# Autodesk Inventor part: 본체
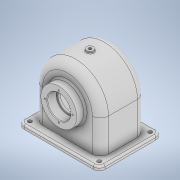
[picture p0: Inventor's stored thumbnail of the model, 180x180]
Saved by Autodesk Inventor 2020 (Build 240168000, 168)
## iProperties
Created: 2022-09
Part Number: 본체
Material: 일반
Document SubType Name: Modeling
Designer: Administrator
Density: 1 g/cm^3
Appearance: 기본값
Mass: 290.05 g
Surface Area: 1046.65 cm^2
Volume: 290.05 cm^3
Author: Administrator
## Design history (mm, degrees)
sketch "스케치1"
  geometry: L1 (70, -54)-(-70, -54); L2 (-70, -54)-(-70, 54); L3 (-70, 54)-(70, 54); L4 (70, 54)-(70, -54); L5 (70, -54)-(-70, 54); L6 (-70, -54)-(70, 54); 1 further point
  constraints: 12 end point, 2 midpoint, 2 parallel, 1 horizontal, 1 perpendicular
  dimensions: "d0" = 140 distance of L2.end L3.end; "d1" = 108 distance of L1.end L2.end
extrude "돌출1" new body sketch "스케치1" distance "d2" = 7; taper "d3" = 0 deg
sketch "스케치2"
  geometry: L1 (70, 0)-(-70, 0) reference; L2 (57, 64)-(57, 3); L3 (-57, 64)-(-57, 3); L4 (-70, 7)-(70, 7) reference; A1 r 57 centre (0, 64) between (57, 64) and (-57, 64); 3 further points
  constraints: 4 end point, 2 point on circle, 2 tangent, 2 vertical, 1 centre point, 1 vertical alignment
  dimensions: "d4" = 114 diameter of A1; "d5" = 64 distance from line of L1 A1.centre
extrude "돌출2" new body sketch "스케치2" stored distance "d6" = 78; taper "d7" = 0 deg
fillet "모깎기1" dims "d8" = 14
feature "쉘1" dims "d9" = 5
sketch "스케치3"
  geometry: L1 (-43, -39)-(43, -39) reference; L2 (57, -25)-(-57, -25) reference; L3 (-57, 25)-(57, 25) reference; L4 (-57, 25)-(-57, -25) reference; L5 (57, -25)-(-57, -25) reference; L6 (57, 25)-(57, -25) reference; L7 (43, 39)-(-43, 39) reference; L8 (-57, 25)-(57, 25) reference; L9 (-43, 34)-(43, 34) reference; L10 (-52, 25)-(-52, -25) reference; L11 (43, -34)-(-43, -34) reference; L12 (52, 25)-(52, -25) reference; A1 r 14 centre (-43, -25) between (-57, -25) and (-43, -39) reference; A2 r 14 centre (43, -25) between (43, -39) and (57, -25) reference; A3 r 14 centre (43, 25) between (57, 25) and (43, 39) reference; A4 r 14 centre (-43, 25) between (-43, 39) and (-57, 25) reference; A5 r 9 centre (-43, -25) between (-52, -25) and (-43, -34) reference; A6 r 9 centre (-43, 25) between (-43, 34) and (-52, 25) reference; A7 r 9 centre (43, -25) between (43, -34) and (52, -25) reference; A8 r 9 centre (43, 25) between (52, 25) and (43, 34) reference; 1 further point
extrude "돌출3" cut sketch "스케치3" distance "d10" = 78; taper "d11" = 0 deg
feature "결합1"
  node "솔리드2"
sketch "스케치4"
  geometry: L1 (64, -73)-(64, 93); L2 (0, 54)-(0, -54) reference; L3 (84, -34)-(84, -20); L4 (92, -20)-(100.083, -34); L5 (107, -34)-(64, -34) reference; L6 (92, -20)-(84, -20); L7 (95, 39)-(95, 54); L8 (95, 54)-(64, 54); L9 (64, 39)-(107, 39) reference; 1 further point
  constraints: 12 end point, 4 point on line, 3 vertical, 2 perpendicular, 1 horizontal
  dimensions: "d12" = 64 distance between parallel lines of L2 L1; "d13" = 60 deg angle of L5 L4; "d14" = 40 diameter of L3 L1; "d15" = 14 distance between parallel lines of L6 L5; "d16" = 56 diameter of L4.start L1; "d17" = 15 distance between parallel lines of L8 L9; "d18" = 62 diameter of L7 L1
revolve "회전1" sketch "스케치4" stored, may be unused: angle "d19" = 90 deg
sketch "스케치5"
  geometry: A1 r 57 centre (0, 0) between (57, 0) and (-57, 0) reference; 2 further points
  constraints: 1 coincident
hole "구멍1" sketch "스케치5" at (0, 0) diameter "d20" = 40; stored, may be unused: countersink angle "d24" = 90 deg, drill point angle "d26" = 0 deg; dims "d21" = 6, "d22" = 64, "d23" = 3, "d25" = 16
sketch "스케치6"
  geometry: C1 r 31 at (0, 0) reference; 2 further points
  constraints: 1 coincident
hole "구멍2" sketch "스케치6" at (0, 0) diameter "d27" = 35; stored, may be unused: countersink angle "d31" = 90 deg, drill point angle "d33" = 0 deg; dims "d28" = 6, "d29" = 40, "d30" = 16, "d32" = 5
node "작업 평면1"
sketch "스케치7"
  geometry: C1 r 6 at (0, 0); 1 further point
  constraints: 1 centre point, 1 coincident
  dimensions: "d35" = 12 diameter of C1
extrude "돌출4" join sketch "스케치7" stored distance "d36" = 78; taper "d37" = 0 deg
sketch "스케치8"
  geometry: C1 r 6 at (0, 0) reference; 2 further points
  constraints: 1 coincident
hole "구멍3" sketch "스케치8" at (0, 0) diameter "d38" = 5.1881; stored, may be unused: countersink angle "d42" = 90 deg, drill point angle "d44" = 0 deg; dims "d39" = 12, "d40" = 40, "d41" = 16, "d43" = 16
fillet "모깎기2" dims "d45" = 10
sketch "스케치9"
  geometry: A1 r 10 centre (60, 44) between (70, 44) and (60, 54) reference; A2 r 10 centre (60, -44) between (60, -54) and (70, -44) reference; A3 r 10 centre (-60, -44) between (-70, -44) and (-60, -54) reference; A4 r 10 centre (-60, 44) between (-60, 54) and (-70, 44) reference; 5 further points
  constraints: 4 coincident
hole "구멍4" sketch "스케치9" at (60, 44), (60, -44), (-60, -44), (-60, 44) diameter "d46" = 6.6; stored, may be unused: countersink angle "d50" = 90 deg, drill point angle "d52" = 0 deg; dims "d47" = 12, "d48" = 40, "d49" = 16, "d51" = 16
chamfer "모따기1" distance "d53" = 1; stored, may be unused: second distance "d54" = 2, angle "d55" = 45 deg
fillet "모깎기3" dims "d56" = 0.6
fillet "모깎기4" dims "d57" = 3, "d84" = 1
sketch "스케치10"
  geometry: L1 (-14, 57)-(-14, 0) reference; L2 (-19, -7)-(-29, -7) reference; 2 further points
  constraints: 1 other
  dimensions: "d58" = 39 distance from line of L1 point (25, 10); "d59" = 17 distance from line of L2 point (25, 10)
feature "엠보싱1" sketch "스케치10" dims "d0" = 140, "d1" = 108, "d60" = 0.5, "d61" = 0
sketch "스케치11" dims "d62" = 48
  geometry: C1 r 31 at (0, 0) reference; C2 r 21 at (0, 0) reference; 3 further points
  constraints: 2 vertical alignment, 1 coincident, 2 other
hole "구멍5" sketch "스케치11" at (0, 24) diameter "d63" = 2.459; stored, may be unused: countersink angle "d67" = 90 deg, drill point angle "d69" = 118 deg; dims "d64" = 7, "d65" = 40, "d66" = 16, "d68" = 9
sketch "스케치12" dims "d73" = 48
  geometry: C1 r 32 at (0, 0) reference; C2 r 21 at (0, 0) reference; 3 further points
  constraints: 2 vertical alignment, 1 coincident, 2 other
hole "구멍6" sketch "스케치12" at (0, 24) diameter "d74" = 2.459; stored, may be unused: countersink angle "d78" = 90 deg, drill point angle "d80" = 118 deg; dims "d75" = 7, "d76" = 40, "d77" = 16, "d79" = 9
node "솔리드1"
pattern_circular "원형 패턴1" dims angle "d71" = 360 deg
pattern_circular "원형 패턴2" dims angle "d82" = 360 deg
node "투영된 루프1"
node "투영된 루프2"
node "투영된 루프3"
feature "A9D066F2-1C7D-4E18-AEED-F7BC21143FA4" dims "d20" = 40, "d21" = 6, "d22" = 64, "d23" = 3, "d24" = 90 deg, "d25" = 16, "d26" = 0
other parameters: "d34" = 124
